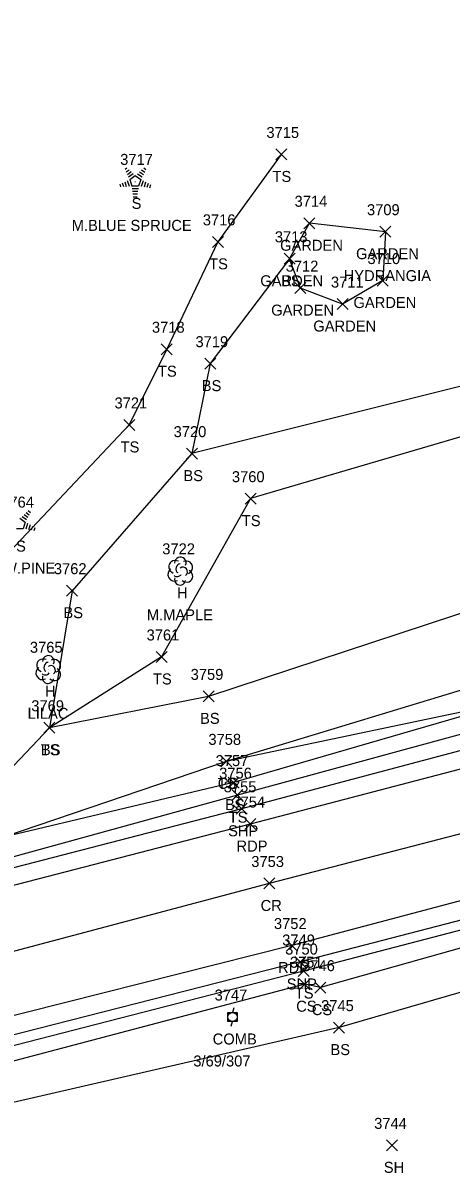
# Model space of a CAD drawing. Extents: x 1520648 to 1523413, y 732854 to 735518.
# Drawn here: x 1521256.7 to 1521334.6, y 733505.9 to 733715.1 of the extents above; entities that cross this region are included whole.
import ezdxf

# ---------------------------------------------------------------- set-up
doc = ezdxf.new("R2010")
doc.units = 0
for name, color, linetype in [('L_A', 7, 'Continuous'), ('L_C', 7, 'Continuous'), ('L_I', 7, 'Continuous'), ('L_TIC', 7, 'Continuous'), ('LAPB', 7, 'Continuous'), ('LELB', 7, 'Continuous'), ('LTC', 7, 'Continuous'), ('LTD', 7, 'Continuous'), ('P_A', 7, 'Continuous'), ('P_I', 7, 'Continuous'), ('P_TIC', 7, 'Continuous'), ('PET', 7, 'Continuous'), ('PRC', 7, 'Continuous'), ('PSP', 7, 'Continuous'), ('U_A', 7, 'Continuous'), ('U_C', 7, 'Continuous'), ('U_I', 7, 'Continuous'), ('UP', 7, 'Continuous')]:
    doc.layers.add(name, color=color, linetype=linetype)

msp = doc.modelspace()

# ---------------------------------------------------------------- linework, layer by layer
at = {"layer": 'L_TIC'}
for points in [[(1521302.7, 733690.16), (1521304.7, 733692.16)], [(1521304.7, 733690.16), (1521302.7, 733692.16)], [(1521307.83, 733677.64), (1521309.83, 733679.64)], [(1521309.83, 733677.64), (1521307.83, 733679.64)], [(1521307.83, 733677.64), (1521309.83, 733679.64)], [(1521309.83, 733677.64), (1521307.83, 733679.64)], [(1521321.67, 733676.11), (1521323.67, 733678.11)], [(1521323.67, 733676.11), (1521321.67, 733678.11)], [(1521321.67, 733676.11), (1521323.67, 733678.11)], [(1521323.67, 733676.11), (1521321.67, 733678.11)], [(1521291.17, 733674.26), (1521293.17, 733676.26)], [(1521293.17, 733674.26), (1521291.17, 733676.26)], [(1521304.23, 733671.18), (1521306.23, 733673.18)], [(1521306.23, 733671.18), (1521304.23, 733673.18)], [(1521304.23, 733671.18), (1521306.23, 733673.18)], [(1521306.23, 733671.18), (1521304.23, 733673.18)], [(1521306.21, 733665.84), (1521308.21, 733667.84)], [(1521308.21, 733665.84), (1521306.21, 733667.84)], [(1521321.19, 733667.22), (1521323.19, 733669.22)], [(1521323.19, 733667.22), (1521321.19, 733669.22)], [(1521313.88, 733662.94), (1521315.88, 733664.94)], [(1521315.88, 733662.94), (1521313.88, 733664.94)], [(1521281.86, 733654.73), (1521283.86, 733656.73)], [(1521283.86, 733654.73), (1521281.86, 733656.73)], [(1521289.8, 733652.1), (1521291.8, 733654.1)], [(1521291.8, 733652.1), (1521289.8, 733654.1)], [(1521275.05, 733640.95), (1521277.05, 733642.95)], [(1521277.05, 733640.95), (1521275.05, 733642.95)], [(1521286.46, 733635.73), (1521288.46, 733637.73)], [(1521288.46, 733635.73), (1521286.46, 733637.73)], [(1521286.46, 733635.73), (1521288.46, 733637.73)], [(1521288.46, 733635.73), (1521286.46, 733637.73)], [(1521297.12, 733627.54), (1521299.12, 733629.54)], [(1521299.12, 733627.54), (1521297.12, 733629.54)], [(1521264.62, 733610.8), (1521266.62, 733612.8)], [(1521266.62, 733610.8), (1521264.62, 733612.8)], [(1521280.94, 733598.74), (1521282.94, 733600.74)], [(1521282.94, 733598.74), (1521280.94, 733600.74)], [(1521289.49, 733591.57), (1521291.49, 733593.57)], [(1521291.49, 733591.57), (1521289.49, 733593.57)], [(1521260.52, 733585.86), (1521262.52, 733587.86)], [(1521262.52, 733585.86), (1521260.52, 733587.86)], [(1521260.52, 733585.86), (1521262.52, 733587.86)], [(1521262.52, 733585.86), (1521260.52, 733587.86)], [(1521260.52, 733585.86), (1521262.52, 733587.86)], [(1521262.52, 733585.86), (1521260.52, 733587.86)], [(1521292.71, 733579.75), (1521294.71, 733581.75)], [(1521294.71, 733579.75), (1521292.71, 733581.75)], [(1521292.71, 733579.75), (1521294.71, 733581.75)], [(1521294.71, 733579.75), (1521292.71, 733581.75)], [(1521294.03, 733575.88), (1521296.03, 733577.88)], [(1521296.03, 733575.88), (1521294.03, 733577.88)], [(1521294.73, 733573.6), (1521296.73, 733575.6)], [(1521296.73, 733573.6), (1521294.73, 733575.6)], [(1521306.77, 733541.6), (1521308.77, 733543.6)], [(1521308.77, 733541.6), (1521306.77, 733543.6)], [(1521306.98, 733539.2), (1521308.98, 733541.2)], [(1521308.98, 733539.2), (1521306.98, 733541.2)], [(1521309.83, 733538.58), (1521311.83, 733540.58)], [(1521311.83, 733538.58), (1521309.83, 733540.58)], [(1521313.23, 733531.31), (1521315.23, 733533.31)], [(1521315.23, 733531.31), (1521313.23, 733533.31)], [(1521322.89, 733509.89), (1521324.89, 733511.89)], [(1521324.89, 733509.89), (1521322.89, 733511.89)]]:
    msp.add_lwpolyline(points, dxfattribs=at)
at = {"layer": 'LAPB'}
for points in [[(1521322.67, 733677.11), (1521322.19, 733668.22), (1521314.88, 733663.94), (1521307.21, 733666.84), (1521305.23, 733672.18), (1521308.83, 733678.64)], [(1521322.67, 733677.11), (1521308.83, 733678.64)]]:
    msp.add_lwpolyline(points, dxfattribs=at)
at = {"layer": 'LELB'}
for points in [[(1521391.43, 733715.08), (1521395.91, 733684.5), (1521401.54, 733667.87), (1521402.17, 733661.87), (1521404.53, 733642.09), (1521399.77, 733626.22), (1521393.85, 733615.3), (1521389.77, 733604.49), (1521375.57, 733598.87), (1521346.27, 733591.74), (1521295.03, 733576.88), (1521253.17, 733566.96), (1521225.68, 733561.04), (1521193.61, 733550.49), (1521146.45, 733540.58), (1521095.03, 733527.62), (1521049.04, 733515.84), (1521035.57, 733513.93), (1521028.78, 733520.1), (1521023.54, 733528.05)], [(1521303.7, 733691.16), (1521292.17, 733675.26), (1521282.86, 733655.73), (1521276.05, 733641.95), (1521253.4, 733617.93), (1521247.63, 733595.18), (1521245.81, 733579.5), (1521238.13, 733579.72)], [(1521305.23, 733672.18), (1521290.8, 733653.1), (1521287.46, 733636.73)], [(1521401.54, 733667.87), (1521352.97, 733653.11), (1521287.46, 733636.73), (1521265.62, 733611.8), (1521261.52, 733586.86)], [(1521402.17, 733661.87), (1521355.62, 733645.41), (1521298.12, 733628.54), (1521281.94, 733599.74), (1521261.52, 733586.86)], [(1521408.35, 733642.84), (1521405.18, 733625.46), (1521399.57, 733613.48), (1521391.63, 733601.72), (1521376.47, 733596.39), (1521348.79, 733589.01), (1521295.73, 733574.6), (1521253.19, 733562.87), (1521227.3, 733556.06), (1521194.61, 733547.59), (1521147.2, 733535.61), (1521095.64, 733522.47), (1521051.1, 733511.97), (1521036.15, 733508.39), (1521030.07, 733511.16), (1521025.66, 733517.9), (1521023.54, 733528.05), (1521020.72, 733532.96)], [(1521399.77, 733626.22), (1521380.58, 733619.54), (1521369.47, 733614.32), (1521340.24, 733608.92), (1521290.49, 733592.57), (1521261.52, 733586.86), (1521251.75, 733576.61), (1521246.79, 733575.04), (1521223.74, 733567.11), (1521190.26, 733560.78), (1521150.76, 733551.63), (1521094.3, 733531.11), (1521048.48, 733523.17)], [(1521393.85, 733615.3), (1521386, 733609.31), (1521373.91, 733603.95), (1521344.45, 733596.1), (1521293.71, 733580.75)], [(1521346.27, 733591.74), (1521293.71, 733580.75), (1521253.17, 733566.96)], [(1521446.76, 733575.98), (1521399.64, 733563.42), (1521368.02, 733555.68), (1521310.83, 733539.58), (1521307.98, 733540.2), (1521245.46, 733523.72), (1521206.2, 733513.3), (1521154.14, 733500.83), (1521129.34, 733494.19)], [(1521367.26, 733558.11), (1521307.77, 733542.6), (1521244.98, 733526.43), (1521205.63, 733516.31), (1521153.31, 733503.05), (1521110.07, 733490.11), (1521103.61, 733488.92)], [(1521370.39, 733548.57), (1521314.23, 733532.31), (1521247.21, 733516.91), (1521208.34, 733506.35), (1521156.26, 733492.33), (1521131.75, 733483.81)]]:
    msp.add_lwpolyline(points, dxfattribs=at)
at = {"layer": 'LTC'}
for p, q in [((1521275.28, 733688.47), (1521275.63, 733688.73)), ((1521275.49, 733688), (1521276.02, 733688.39)), ((1521278.3, 733688.36), (1521278.85, 733687.96)), ((1521278.67, 733688.71), (1521279.09, 733688.41)), ((1521275.68, 733686.4), (1521276.01, 733685.38)), ((1521275.7, 733687.54), (1521276.4, 733688.05)), ((1521275.91, 733687.07), (1521276.78, 733687.71)), ((1521276.13, 733686.62), (1521277.14, 733687.35)), ((1521276.13, 733686.62), (1521276.52, 733685.42)), ((1521277.14, 733687.35), (1521278.14, 733686.63)), ((1521277.56, 733687.66), (1521278.37, 733687.08)), ((1521278.14, 733686.63), (1521277.75, 733685.42)), ((1521277.93, 733688.01), (1521278.61, 733687.52)), ((1521278.58, 733686.36), (1521278.24, 733685.32)), ((1521274.31, 733685.75), (1521274.46, 733685.28)), ((1521274.76, 733685.97), (1521274.98, 733685.31)), ((1521275.22, 733686.18), (1521275.49, 733685.35)), ((1521277.75, 733685.42), (1521276.52, 733685.42)), ((1521277.71, 733684.92), (1521276.56, 733684.92)), ((1521277.63, 733684.42), (1521276.64, 733684.42)), ((1521279.02, 733686.11), (1521278.73, 733685.22)), ((1521279.47, 733685.86), (1521279.23, 733685.13)), ((1521279.91, 733685.61), (1521279.72, 733685.03)), ((1521277.54, 733683.92), (1521276.71, 733683.92)), ((1521277.46, 733683.42), (1521276.78, 733683.42)), ((1521256.9, 733625.66), (1521257.58, 733625.17)), ((1521257.27, 733626.01), (1521257.82, 733625.61)), ((1521257.64, 733626.36), (1521258.06, 733626.05)), ((1521256.11, 733625), (1521257.11, 733624.28)), ((1521256.53, 733625.31), (1521257.34, 733624.73)), ((1521257.11, 733624.28), (1521256.72, 733623.07)), ((1521257.54, 733624.01), (1521257.21, 733622.97)), ((1521257.99, 733623.75), (1521257.7, 733622.87)), ((1521258.43, 733623.5), (1521258.2, 733622.78)), ((1521256.72, 733623.07), (1521255.49, 733623.07)), ((1521258.88, 733623.25), (1521258.69, 733622.68))]:
    msp.add_line(p, q, dxfattribs=at)
at = {"layer": 'LTD'}
for p, q in [((1521285.31, 733615.41), (1521285.31, 733615.41)), ((1521285.31, 733615.41), (1521285.31, 733615.41)), ((1521261.27, 733597.5), (1521261.27, 733597.5)), ((1521261.27, 733597.5), (1521261.27, 733597.5))]:
    msp.add_line(p, q, dxfattribs=at)
for centre in [(1521285.35, 733616.85), (1521261.32, 733598.94)]:
    msp.add_arc(centre, 1.05, 335.5272, 180.9563, dxfattribs=at)
for centre, major_axis, ratio, start_param, end_param in [((1521284.52, 733616.08), (1.21, -0.51), 0.895232, 1.570796, 4.712389), ((1521286.35, 733616), (-1.14, -0.48), 0.949671, 1.570796, 4.712389), ((1521284.22, 733614.71), (0.58, -1.04), 0.959034, 3.141593, 6.283185), ((1521285.1, 733615.87), (-0.208, -0.792), 0.645439, 3.141593, 6.283185), ((1521285.81, 733615.25), (-0.5, 0.667), 0.989748, 3.141593, 6.283185), ((1521286.31, 733614.58), (-1.09, 0.79), 0.841452, 1.570796, 4.712389), ((1521285.31, 733613.91), (0.26, 1.06), 0.942809, 1.570796, 4.712389), ((1521284.85, 733614.66), (-0.625, -0.083), 0.423636, 0, 3.141593), ((1521260.48, 733598.17), (1.21, -0.51), 0.895232, 1.570796, 4.712389), ((1521261.06, 733597.96), (-0.208, -0.792), 0.645439, 3.141593, 6.283185), ((1521262.31, 733598.09), (-1.14, -0.48), 0.949671, 1.570796, 4.712389), ((1521260.19, 733596.79), (0.58, -1.04), 0.959034, 3.141593, 6.283185), ((1521260.81, 733596.75), (-0.625, -0.083), 0.423636, 0, 3.141593), ((1521261.77, 733597.34), (-0.5, 0.667), 0.989748, 3.141593, 6.283185), ((1521262.27, 733596.67), (-1.09, 0.79), 0.841452, 1.570796, 4.712389), ((1521261.27, 733596), (0.26, 1.06), 0.942809, 1.570796, 4.712389)]:
    msp.add_ellipse(centre, major_axis=major_axis, ratio=ratio, start_param=start_param, end_param=end_param, dxfattribs=at)
at = {"layer": 'P_TIC'}
for points in [[(1521295.5, 733571.12), (1521297.5, 733573.12)], [(1521297.5, 733571.12), (1521295.5, 733573.12)], [(1521297.08, 733568.34), (1521299.08, 733570.34)], [(1521299.08, 733568.34), (1521297.08, 733570.34)], [(1521300.52, 733557.53), (1521302.52, 733559.53)], [(1521302.52, 733557.53), (1521300.52, 733559.53)], [(1521304.64, 733546.24), (1521306.64, 733548.24)], [(1521306.64, 733546.24), (1521304.64, 733548.24)], [(1521306.16, 733543.25), (1521308.16, 733545.25)], [(1521308.16, 733543.25), (1521306.16, 733545.25)]]:
    msp.add_lwpolyline(points, dxfattribs=at)
at = {"layer": 'PET'}
for points in [[(1521359.51, 733585.39), (1521298.08, 733569.34), (1521228.86, 733551.45), (1521196.2, 733542.53), (1521147.39, 733530.28), (1521096.51, 733517.17), (1521058.61, 733507.66), (1520970.9, 733484.81), (1520924.79, 733472.7), (1520867.06, 733456.98), (1520832.23, 733448.09), (1520775.63, 733432.52), (1520733.45, 733421.44), (1520673.24, 733405.46)], [(1521365.83, 733563.19), (1521305.64, 733547.24), (1521243.51, 733531.59), (1521203.56, 733520.88), (1521152.14, 733507.85), (1521105.31, 733495.85), (1521097.86, 733494.19), (1521063.42, 733485.34), (1521018.35, 733473.43), (1520975.95, 733462.3), (1520931.61, 733450.37), (1520885.35, 733438.14), (1520856.88, 733430.56), (1520818.39, 733420.77), (1520780.83, 733410.61), (1520744.81, 733401.09), (1520678.56, 733383.16)]]:
    msp.add_lwpolyline(points, dxfattribs=at)
at = {"layer": 'PRC'}
msp.add_lwpolyline([(1521363.3, 733574.52), (1521301.52, 733558.53), (1521239.8, 733542.16), (1521200.1, 733531.63), (1521149.34, 733518.97), (1521098.13, 733505.5), (1521061.28, 733496.8), (1521014.81, 733484.07), (1520973.92, 733473.61), (1520928.9, 733461.35), (1520870.34, 733445.92), (1520824.04, 733433.72), (1520778.39, 733421.36), (1520737.02, 733410.36), (1520676.97, 733394.51)], dxfattribs=at)
at = {"layer": 'PSP'}
for points in [[(1521358.34, 733588.53), (1521296.5, 733572.12), (1521227.74, 733554.37), (1521195.21, 733545.64), (1521147.51, 733533.73), (1521095.86, 733520.25), (1521076.01, 733514.97), (1521056.93, 733511.88), (1521033.51, 733506.4), (1520966.21, 733488.2), (1520925.69, 733476.27), (1520866.08, 733460.02), (1520832.2, 733451.33), (1520773.75, 733436.48), (1520732.76, 733424.74), (1520671.96, 733408.83)], [(1521366.85, 733559.74), (1521307.16, 733544.25), (1521244.3, 733528.24), (1521204.94, 733517.79), (1521152.82, 733504.37), (1521106.57, 733492.89), (1521080.1, 733485.88), (1521063.46, 733481.98), (1521018.86, 733470.55), (1520976.52, 733459.1), (1520931.66, 733447.13), (1520886.57, 733435.14), (1520877.93, 733432.71), (1520850.75, 733426.02), (1520817.82, 733417.13), (1520781.5, 733407.41), (1520747.69, 733397.94), (1520743.14, 733395.11), (1520720.82, 733389.47), (1520716.87, 733390.02), (1520705.4, 733386.95), (1520679.31, 733380.34)]]:
    msp.add_lwpolyline(points, dxfattribs=at)
at = {"layer": 'UP'}
for p, q in [((1521295.09, 733535.91), (1521294.84, 733535.08)), ((1521294.01, 733533.41), (1521294.01, 733535.08)), ((1521294.01, 733535.08), (1521295.68, 733535.08)), ((1521294.84, 733534.24), (1521294.84, 733534.24)), ((1521295.68, 733535.08), (1521295.68, 733533.41)), ((1521295.68, 733533.41), (1521294.01, 733533.41)), ((1521294.59, 733532.58), (1521294.84, 733533.41))]:
    msp.add_line(p, q, dxfattribs=at)
msp.add_circle((1521294.84, 733534.24), 0.833, dxfattribs=at)

# ---------------------------------------------------------------- texts
at = {"layer": 'L_A'}
for s, p in [('TS', (1521302.11, 733686.16)), ('S', (1521276.47, 733681.26)), ('GARDEN', (1521303.5, 733673.64)), ('GARDEN', (1521303.5, 733673.64)), ('GARDEN', (1521317.33, 733672.11)), ('GARDEN', (1521317.33, 733672.11)), ('TS', (1521290.58, 733670.26)), ('GARDEN', (1521299.9, 733667.18)), ('BS', (1521303.67, 733667.18)), ('GARDEN', (1521301.88, 733661.84)), ('GARDEN', (1521316.86, 733663.22)), ('GARDEN', (1521309.55, 733658.94)), ('TS', (1521281.27, 733650.73)), ('BS', (1521289.24, 733648.1)), ('TS', (1521274.46, 733636.95)), ('BS', (1521285.9, 733631.73)), ('BS', (1521285.9, 733631.73)), ('TS', (1521296.53, 733623.54)), ('S', (1521255.44, 733618.91)), ('H', (1521284.74, 733610.41)), ('BS', (1521264.06, 733606.8)), ('TS', (1521280.35, 733594.74)), ('H', (1521260.7, 733592.5)), ('BS', (1521288.93, 733587.57)), ('TS', (1521259.93, 733581.86)), ('BS', (1521259.96, 733581.86)), ('BS', (1521259.96, 733581.86)), ('TS', (1521292.12, 733575.75)), ('CS', (1521292.15, 733575.75)), ('BS', (1521293.47, 733571.88)), ('TS', (1521294.14, 733569.6)), ('TS', (1521306.18, 733537.6)), ('CS', (1521306.43, 733535.2)), ('CS', (1521309.27, 733534.58)), ('BS', (1521312.67, 733527.31)), ('SH', (1521322.38, 733505.89))]:
    msp.add_text(s, height=2, dxfattribs=at).set_placement(p)
at = {"layer": 'L_C'}
for s, p in [('M.BLUE SPRUCE', (1521265.57, 733677.26)), ('HYDRANGIA', (1521315.07, 733668.11)), ('HYDRANGIA', (1521315.07, 733668.11)), ('M.W.PINE', (1521250.1, 733614.91)), ('M.MAPLE', (1521279.24, 733606.41)), ('LILAC', (1521257.54, 733588.5))]:
    msp.add_text(s, height=2, dxfattribs=at).set_placement(p)
at = {"layer": 'L_I'}
for s, p in [('3715', (1521301.01, 733694.16)), ('3717', (1521274.39, 733689.26)), ('3714', (1521306.14, 733681.64)), ('3714', (1521306.14, 733681.64)), ('3709', (1521319.32, 733680.11)), ('3709', (1521319.32, 733680.11)), ('3716', (1521289.43, 733678.26)), ('3713', (1521302.54, 733675.18)), ('3713', (1521302.54, 733675.18)), ('3712', (1521304.52, 733669.84)), ('3710', (1521319.41, 733671.22)), ('3711', (1521312.76, 733666.94)), ('3718', (1521280.17, 733658.73)), ('3719', (1521288.1, 733656.1)), ('3721', (1521273.36, 733644.95)), ('3720', (1521284.12, 733639.73)), ('3720', (1521284.12, 733639.73)), ('3760', (1521294.73, 733631.54)), ('3764', (1521252.74, 733626.91)), ('3722', (1521282.05, 733618.41)), ('3762', (1521262.32, 733614.8)), ('3761', (1521279.2, 733602.74)), ('3765', (1521257.96, 733600.5)), ('3759', (1521287.22, 733595.57)), ('3769', (1521258.21, 733589.86)), ('3769', (1521258.21, 733589.86)), ('3769', (1521258.21, 733589.86)), ('3758', (1521290.45, 733583.75)), ('3758', (1521290.45, 733583.75)), ('3757', (1521291.77, 733579.88)), ('3756', (1521292.41, 733577.6)), ('3750', (1521304.42, 733545.6)), ('3751', (1521305.29, 733543.2)), ('3746', (1521307.52, 733542.58)), ('3745', (1521310.97, 733535.31)), ('3744', (1521320.63, 733513.89))]:
    msp.add_text(s, height=2, dxfattribs=at).set_placement(p)
at = {"layer": 'LTC'}
msp.add_text('.', height=1.04, rotation=270, dxfattribs=at).set_placement((1521277.02, 733686.37))
at = {"layer": 'P_A'}
for s, p in [('SHP', (1521294.04, 733567.12)), ('RDP', (1521295.56, 733564.34)), ('CR', (1521299.96, 733553.53)), ('RDP', (1521303.13, 733542.24)), ('SHP', (1521304.7, 733539.25))]:
    msp.add_text(s, height=2, dxfattribs=at).set_placement(p)
at = {"layer": 'P_I'}
for s, p in [('3755', (1521293.24, 733575.12)), ('3754', (1521294.82, 733572.34)), ('3753', (1521298.26, 733561.53)), ('3752', (1521302.38, 733550.24)), ('3749', (1521303.89, 733547.25))]:
    msp.add_text(s, height=2, dxfattribs=at).set_placement(p)
at = {"layer": 'U_A'}
msp.add_text('COMB', height=2, dxfattribs=at).set_placement((1521291.23, 733529.24))
at = {"layer": 'U_C'}
msp.add_text('3/69/307', height=2, dxfattribs=at).set_placement((1521287.71, 733525.24))
at = {"layer": 'U_I'}
msp.add_text('3747', height=2, dxfattribs=at).set_placement((1521291.58, 733537.24))

doc.saveas('drawing.dxf')
